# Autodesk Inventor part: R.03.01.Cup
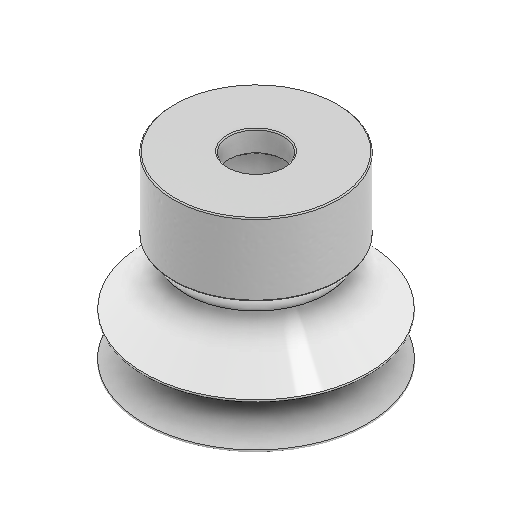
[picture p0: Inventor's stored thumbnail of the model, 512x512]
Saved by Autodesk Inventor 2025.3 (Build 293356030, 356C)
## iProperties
Created: 2021-02
Part Number: R.03.01.Cup
Material: PET Plastic
Document SubType Name: Modeling
Designer: Михальчик
Density: 1.541 g/cm^3
Appearance: Bianco
Author: Михальчик
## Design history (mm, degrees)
sketch "Sketch1"
  geometry: L1 (10, -7.5)-(16.5, -7.5); L2 (16.5, -7.5)-(16.5, -2.5); L3 (16.5, -2.5)-(14.5, -2.5); L4 (14.5, -2.5)-(14.5, -3.5); L5 (14.5, -3.5)-(10.75, -3.5); L6 (10.75, -3.5)-(10.75, -2.5); L7 (2.5, -4)-(4, -7.75); L8 (4, -7.75)-(7.5, -4); L9 (7.5, -4)-(8.375, -4.875); L10 (8.375, -4.875)-(10.75, -2.5); L11 (0, -10.25)-(4, -10.25); L12 (0, -12.355)-(0, 2.059) reference; L13 (2.5, -4)-(7.5, -4); L14 (4, -7.75)-(4, -10.25); L15 (2.5, -4)-(2.5, -6.5); L16 (7.5, -4)-(7.5, -5); L17 (0, 0)-(19.203, 0); L18 (3.907, -10.186)-(2.5, -6.5); L19 (2.5, -6.5)-(0.131, -10.215); L20 (2.5, -4)-(-0.046, -10.123); L21 (0.047, -10.161)-(0, -10.25); L22 (10, -7.5)-(8.375, -6.362); L23 (8.375, -6.362)-(4.084, -10.205); L24 (8.375, -6.362)-(8.375, -4.875); A1 r 0.1 centre (4, -10.15) between (3.907, -10.186) and (4.084, -10.205); A2 r 0.1 centre (0.047, -10.161) between (-0.046, -10.123) and (0.131, -10.215)
  constraints: 46 end point, 6 point on circle, 5 perpendicular, 5 vertical, 4 horizontal, 3 point on line, 3 tangent, 2 centre point, 1 equal radius, 1 parallel
  dimensions: "d0" = 16.5 distance from line of L11.start L2; "d1" = 7.5 distance from line of L17.start L1; "d2" = 10.25 distance from line of L17.start L11; "d3" = 2.5 distance from line of L17.start L3; "d4" = 3.5 distance from line of L17.start L5; "d5" = 3.75 distance between parallel lines of L4 L6; "d6" = 2 distance between parallel lines of L2 L4; "d8" = 4 distance from line of L17.start L13; "d9" = 2.5 distance from line of L12 L7.start; "d10" = 5 distance of L7.start L8.end; "d11" = 4 distance of L11.start L11.end; "d12" = 6.5 vertical distance of L17.start L15.end; "d14" = 0.1 radius of A1; "d16" = 6.5 distance of L1.start L1.end; "d17" = 145 deg angle of L22 L1
revolve "Revolution1" sketch "Sketch1" stored, may be unused: angle "d13" = 360 deg
fillet "Fillet1" dims "d15" = 0.1
body "Solid1"
